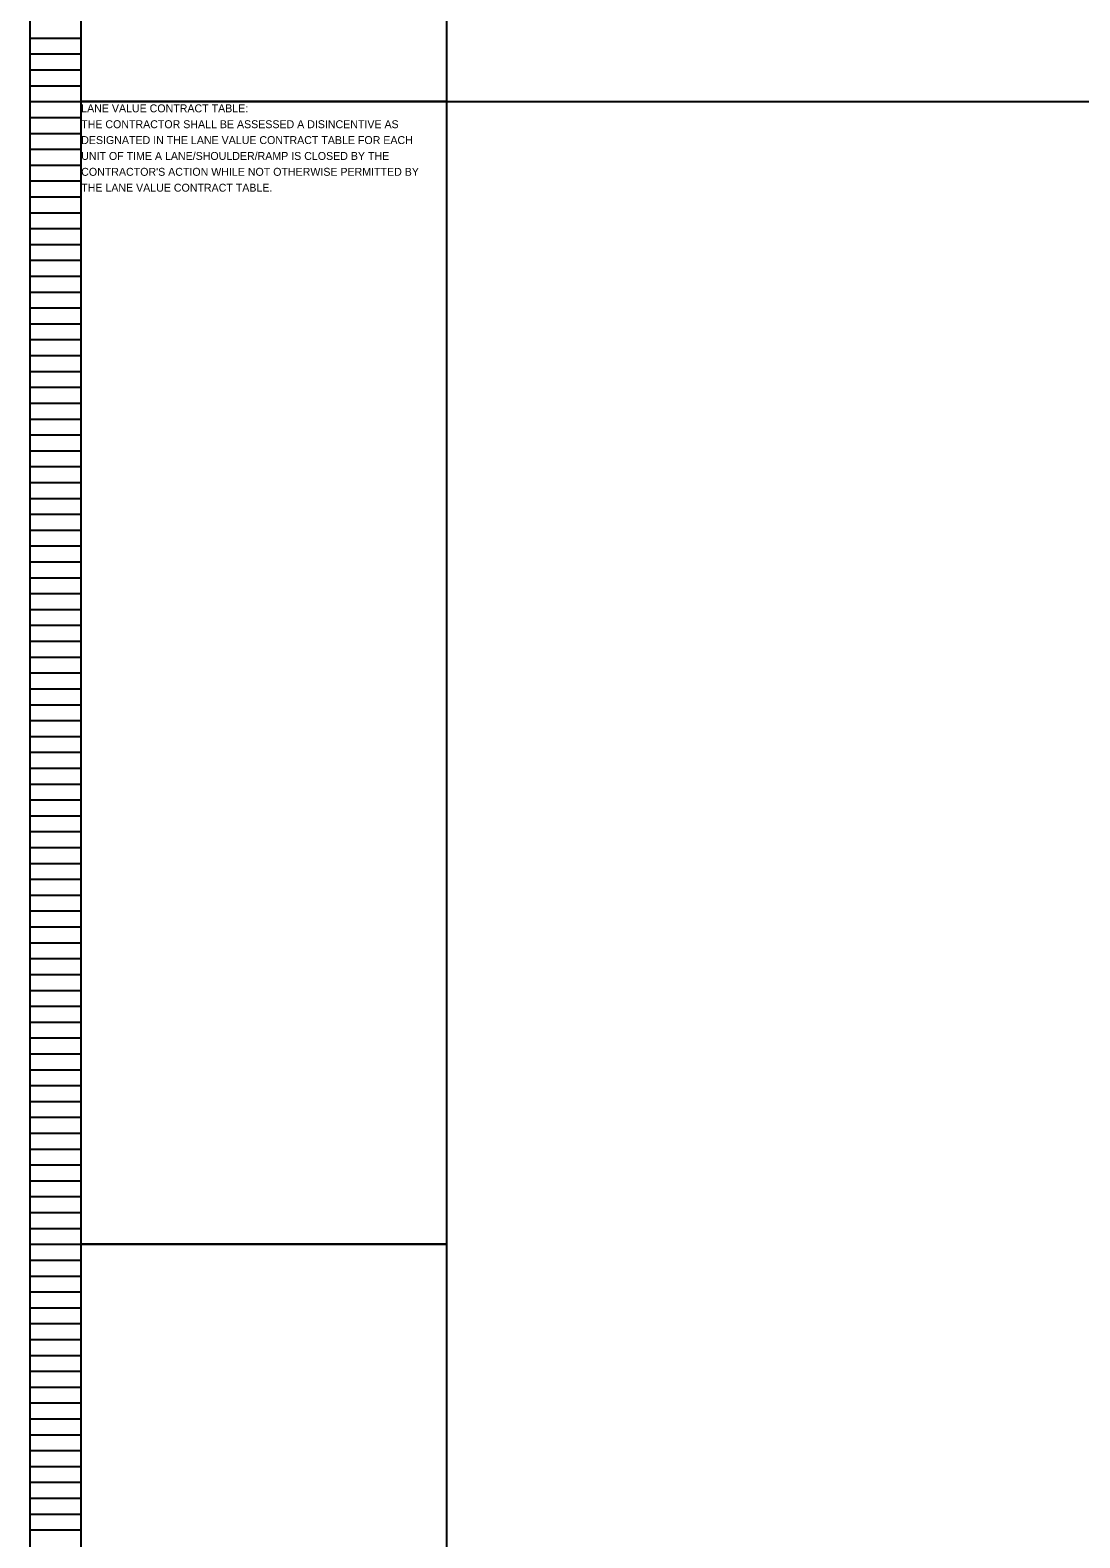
# Model space of a CAD drawing. Extents: x 16463 to 16500, y 5400 to 5823.
# Drawn here: x 16463.05 to 16481.55, y 5717.49 to 5744.09 of the extents above; entities that cross this region are included whole.
import ezdxf

# ---------------------------------------------------------------- set-up
doc = ezdxf.new("R2010")
doc.units = 0
for name, color, linetype in [('Default', 7, 'Continuous'), ('SC_Scratch1', 7, 'Continuous'), ('SH_Data', 7, 'Continuous')]:
    doc.layers.add(name, color=color, linetype=linetype)

msp = doc.modelspace()

# ---------------------------------------------------------------- linework, layer by layer
at = {"layer": 'SC_Scratch1'}
msp.add_line((16470.389, 5742.832), (16500.06, 5742.832), dxfattribs=at)
for points in [[(16463.949, 5762.992), (16470.389, 5762.992), (16470.389, 5742.832), (16463.949, 5742.832)], [(16463.949, 5742.832), (16470.389, 5742.832), (16470.389, 5722.672), (16463.949, 5722.672)], [(16463.949, 5722.672), (16470.389, 5722.672), (16470.389, 5702.512), (16463.949, 5702.512)]]:
    msp.add_lwpolyline(points, close=True, dxfattribs=at)
at = {"layer": 'SH_Data'}
for p, q in [((16463.049, 5742.832), (16463.049, 5762.992)), ((16463.949, 5742.832), (16463.949, 5762.992)), ((16463.049, 5743.952), (16463.949, 5743.952)), ((16463.049, 5743.672), (16463.949, 5743.672)), ((16463.049, 5743.392), (16463.949, 5743.392)), ((16463.049, 5743.112), (16463.949, 5743.112)), ((16463.049, 5722.672), (16463.049, 5742.832)), ((16463.049, 5742.832), (16463.949, 5742.832)), ((16463.049, 5742.832), (16463.949, 5742.832)), ((16463.949, 5722.672), (16463.949, 5742.832)), ((16463.049, 5742.552), (16463.949, 5742.552)), ((16463.049, 5742.272), (16463.949, 5742.272)), ((16463.049, 5741.992), (16463.949, 5741.992)), ((16463.049, 5741.712), (16463.949, 5741.712)), ((16463.049, 5741.432), (16463.949, 5741.432)), ((16463.049, 5741.152), (16463.949, 5741.152)), ((16463.049, 5740.872), (16463.949, 5740.872)), ((16463.049, 5740.592), (16463.949, 5740.592)), ((16463.049, 5740.312), (16463.949, 5740.312)), ((16463.049, 5740.032), (16463.949, 5740.032)), ((16463.049, 5739.752), (16463.949, 5739.752)), ((16463.049, 5739.472), (16463.949, 5739.472)), ((16463.049, 5739.192), (16463.949, 5739.192)), ((16463.049, 5738.912), (16463.949, 5738.912)), ((16463.049, 5738.632), (16463.949, 5738.632)), ((16463.049, 5738.352), (16463.949, 5738.352)), ((16463.049, 5738.072), (16463.949, 5738.072)), ((16463.049, 5737.792), (16463.949, 5737.792)), ((16463.049, 5737.512), (16463.949, 5737.512)), ((16463.049, 5737.232), (16463.949, 5737.232)), ((16463.049, 5736.952), (16463.949, 5736.952)), ((16463.049, 5736.672), (16463.949, 5736.672)), ((16463.049, 5736.392), (16463.949, 5736.392)), ((16463.049, 5736.112), (16463.949, 5736.112)), ((16463.049, 5735.832), (16463.949, 5735.832)), ((16463.049, 5735.552), (16463.949, 5735.552)), ((16463.049, 5735.272), (16463.949, 5735.272)), ((16463.049, 5734.992), (16463.949, 5734.992)), ((16463.049, 5734.712), (16463.949, 5734.712)), ((16463.049, 5734.432), (16463.949, 5734.432)), ((16463.049, 5734.152), (16463.949, 5734.152)), ((16463.049, 5733.872), (16463.949, 5733.872)), ((16463.049, 5733.592), (16463.949, 5733.592)), ((16463.049, 5733.312), (16463.949, 5733.312)), ((16463.049, 5733.032), (16463.949, 5733.032)), ((16463.049, 5732.752), (16463.949, 5732.752)), ((16463.049, 5732.472), (16463.949, 5732.472)), ((16463.049, 5732.192), (16463.949, 5732.192)), ((16463.049, 5731.912), (16463.949, 5731.912)), ((16463.049, 5731.632), (16463.949, 5731.632)), ((16463.049, 5731.352), (16463.949, 5731.352)), ((16463.049, 5731.072), (16463.949, 5731.072)), ((16463.049, 5730.792), (16463.949, 5730.792)), ((16463.049, 5730.512), (16463.949, 5730.512)), ((16463.049, 5730.232), (16463.949, 5730.232)), ((16463.049, 5729.952), (16463.949, 5729.952)), ((16463.049, 5729.672), (16463.949, 5729.672)), ((16463.049, 5729.392), (16463.949, 5729.392)), ((16463.049, 5729.112), (16463.949, 5729.112)), ((16463.049, 5728.832), (16463.949, 5728.832)), ((16463.049, 5728.552), (16463.949, 5728.552)), ((16463.049, 5728.272), (16463.949, 5728.272)), ((16463.049, 5727.992), (16463.949, 5727.992)), ((16463.049, 5727.712), (16463.949, 5727.712)), ((16463.049, 5727.432), (16463.949, 5727.432)), ((16463.049, 5727.152), (16463.949, 5727.152)), ((16463.049, 5726.872), (16463.949, 5726.872)), ((16463.049, 5726.592), (16463.949, 5726.592)), ((16463.049, 5726.312), (16463.949, 5726.312)), ((16463.049, 5726.032), (16463.949, 5726.032)), ((16463.049, 5725.752), (16463.949, 5725.752)), ((16463.049, 5725.472), (16463.949, 5725.472)), ((16463.049, 5725.192), (16463.949, 5725.192)), ((16463.049, 5724.912), (16463.949, 5724.912)), ((16463.049, 5724.632), (16463.949, 5724.632)), ((16463.049, 5724.352), (16463.949, 5724.352)), ((16463.049, 5724.072), (16463.949, 5724.072)), ((16463.049, 5723.792), (16463.949, 5723.792)), ((16463.049, 5723.512), (16463.949, 5723.512)), ((16463.049, 5723.232), (16463.949, 5723.232)), ((16463.049, 5722.952), (16463.949, 5722.952)), ((16463.049, 5702.512), (16463.049, 5722.672)), ((16463.049, 5722.672), (16463.949, 5722.672)), ((16463.049, 5722.672), (16463.949, 5722.672)), ((16463.949, 5702.512), (16463.949, 5722.672)), ((16463.049, 5722.392), (16463.949, 5722.392)), ((16463.049, 5722.112), (16463.949, 5722.112)), ((16463.049, 5721.832), (16463.949, 5721.832)), ((16463.049, 5721.552), (16463.949, 5721.552)), ((16463.049, 5721.272), (16463.949, 5721.272)), ((16463.049, 5720.992), (16463.949, 5720.992)), ((16463.049, 5720.712), (16463.949, 5720.712)), ((16463.049, 5720.432), (16463.949, 5720.432)), ((16463.049, 5720.152), (16463.949, 5720.152)), ((16463.049, 5719.872), (16463.949, 5719.872)), ((16463.049, 5719.592), (16463.949, 5719.592)), ((16463.049, 5719.312), (16463.949, 5719.312)), ((16463.049, 5719.032), (16463.949, 5719.032)), ((16463.049, 5718.752), (16463.949, 5718.752)), ((16463.049, 5718.472), (16463.949, 5718.472)), ((16463.049, 5718.192), (16463.949, 5718.192)), ((16463.049, 5717.912), (16463.949, 5717.912)), ((16463.049, 5717.632), (16463.949, 5717.632))]:
    msp.add_line(p, q, dxfattribs=at)

# ---------------------------------------------------------------- texts
at = {"layer": 'Default'}
for s, p in [('LANE VALUE CONTRACT TABLE:', (16463.949, 5742.643)), ('THE CONTRACTOR SHALL BE ASSESSED A DISINCENTIVE AS ', (16463.949, 5742.363)), ('DESIGNATED IN THE LANE VALUE CONTRACT TABLE FOR EACH ', (16463.949, 5742.083)), ('UNIT OF TIME A LANE/SHOULDER/RAMP IS CLOSED BY THE ', (16463.949, 5741.803)), ("CONTRACTOR'S ACTION WHILE NOT OTHERWISE PERMITTED BY ", (16463.949, 5741.523)), ('THE LANE VALUE CONTRACT TABLE.', (16463.949, 5741.243))]:
    msp.add_text(s, height=0.14, dxfattribs=at).set_placement(p)

doc.saveas('drawing.dxf')
